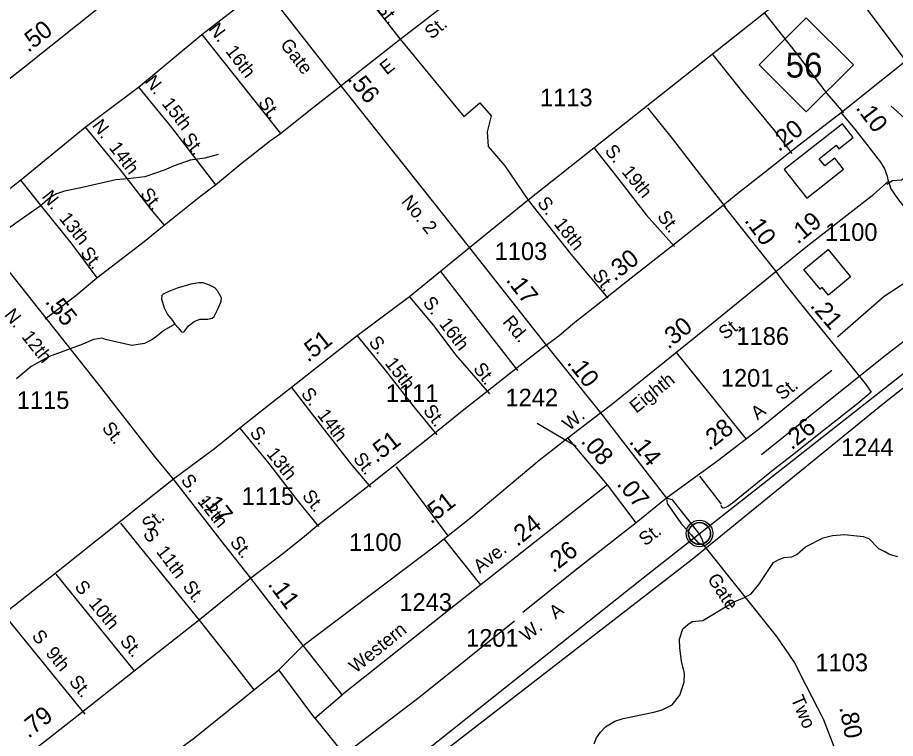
# Model space of a CAD drawing. Extents: x 2056842 to 2160602, y 826753 to 1016856.
# Drawn here: x 2067778 to 2073990, y 864781 to 869878 of the extents above; entities that cross this region are included whole.
import ezdxf

# ---------------------------------------------------------------- set-up
doc = ezdxf.new("R2010")
doc.units = 0
for name, color, linetype in [('Exist Boundary Land Use Reservation Military US Department of Defense', 7, 'Continuous'), ('Exist Civil Demographics Community CELL', 7, 'Continuous'), ('Exist Cultural Warehouse Building Footprint', 7, 'Continuous'), ('Exist Hydrographic Creek Single Shore', 7, 'Continuous'), ('Exist Hydrographic Misc Water Feature', 7, 'Continuous'), ('Exist Railroad Mainline', 7, 'Continuous'), ('Exist Railroad Siding', 7, 'Continuous'), ('Exist Road Non-System Type 51', 7, 'Continuous'), ('Exist Road Non-System Type 51 Label', 7, 'Continuous'), ('Exist Road Primary NC Attributed', 7, 'Continuous'), ('Exist Road Primary NC Service Mileage Hundredths English Label', 7, 'Continuous'), ('Exist Road Primary NC Shield CELL', 7, 'Continuous'), ('Exist Road Primary NC Shield Number Label', 7, 'Continuous'), ('Exist Road Secondary Mileage Hundredths English Label', 7, 'Continuous'), ('Exist Road Secondary Type 51 Attributed', 7, 'Continuous'), ('Exist Road Secondary Type 51 Divided Attributed', 7, 'Continuous'), ('Exist Road Secondary Type 51 Label', 7, 'Continuous'), ('Exist Road Secondary Type 51 Number Label', 7, 'Continuous')]:
    doc.layers.add(name, color=color, linetype=linetype)

msp = doc.modelspace()

# ---------------------------------------------------------------- linework, layer by layer
at = {"layer": 'Exist Boundary Land Use Reservation Military US Department of Defense'}
msp.add_lwpolyline([(2079729.3, 873057.2), (2079217.9, 872231.6), (2078917.6, 871495.8), (2078852.5, 871275.5), (2078751.7, 871162.9), (2076995.4, 869694.7), (2075448.8, 868458.6), (2072205.6, 865914.9), (2069683.3, 863910.7), (2068119, 862645.9), (2067327.2, 862021.6)], dxfattribs=at)
at = {"layer": 'Exist Civil Demographics Community CELL'}
msp.add_lwpolyline([(2072526, 866242.3), (2072527, 866247.9), (2072528.8, 866254.5), (2072531.7, 866261.7), (2072534.6, 866267.4), (2072538, 866273.2), (2072541.7, 866278.3), (2072545.7, 866282.6), (2072550.3, 866287.2), (2072555.8, 866291.8), (2072561.2, 866295.5), (2072566.1, 866298.4), (2072571.2, 866300.8), (2072576.6, 866303.1), (2072582.3, 866304.9), (2072586.6, 866306.1), (2072591.5, 866306.8), (2072595.6, 866307.5), (2072601.9, 866307.8), (2072606.4, 866307.7), (2072612, 866307.4), (2072616.9, 866306.7), (2072621.9, 866305.7), (2072626.9, 866304.3), (2072632, 866302.4), (2072638.7, 866299.4), (2072644.9, 866296), (2072650, 866292.4), (2072655.2, 866288.4), (2072658.5, 866285.3), (2072662.6, 866280.9), (2072666.5, 866276.2), (2072669.5, 866271.6), (2072672.7, 866266.6), (2072675.1, 866261.4), (2072677.2, 866256.4), (2072678.7, 866251.4), (2072680, 866246.8), (2072681.1, 866240.7), (2072681.7, 866236.1), (2072682, 866230.1), (2072681.8, 866224.3), (2072681.2, 866218.6), (2072680.3, 866213.1), (2072678.7, 866206.9), (2072676.8, 866201.1), (2072674.5, 866196), (2072671.3, 866190), (2072668, 866184.7), (2072664.6, 866180), (2072660.4, 866175.3), (2072655.1, 866170.3), (2072650.1, 866166.2), (2072645, 866162.7), (2072640.7, 866160.2), (2072633.9, 866157), (2072626.8, 866154.3), (2072620.8, 866152.8), (2072614.2, 866151.5), (2072609.8, 866151.1), (2072605.3, 866150.8), (2072599.7, 866150.8), (2072595.4, 866151.2), (2072589.8, 866151.9), (2072583.9, 866153.2), (2072579.3, 866154.5), (2072574.1, 866156.4), (2072569.5, 866158.4), (2072565.6, 866160.7), (2072558.8, 866164.7), (2072553.2, 866169), (2072548.3, 866173.5), (2072543.8, 866178.3), (2072540.7, 866182.3), (2072537.7, 866186.5), (2072533.6, 866193.6), (2072531.9, 866197.1), (2072530.2, 866201.1), (2072527.6, 866209.3), (2072526, 866216.4), (2072525.3, 866221.5), (2072525, 866227.9), (2072525, 866232.6), (2072525.5, 866239)], close=True, dxfattribs=at)
for centre, radius in [((2072603.6, 866229.9), 94.3), ((2072603.4, 866230.2), 76.7)]:
    msp.add_circle(centre, radius, dxfattribs=at)
at = {"layer": 'Exist Cultural Warehouse Building Footprint'}
for points in [[(2073614.1, 869127.4), (2073203.4, 868803.4), (2073362.8, 868601.2), (2073623.1, 868806.5), (2073561.3, 868884.8), (2073490.9, 868829.3), (2073451, 868879.9), (2073571.1, 868974.6), (2073590.1, 868950.6), (2073690.9, 869030.1)], [(2073512.7, 868237.5), (2073672.1, 868044.1), (2073516, 867915.3), (2073471.4, 867969.4), (2073457.7, 867958.1), (2073342.8, 868097.5)]]:
    msp.add_lwpolyline(points, close=True, dxfattribs=at)
at = {"layer": 'Exist Hydrographic Creek Single Shore'}
for points in [[(2069198.2, 868909.3), (2069104.7, 868883), (2069000.5, 868870.8), (2068886.7, 868830.4), (2068816.4, 868798.5), (2068678.8, 868752.4), (2068558.6, 868738.1), (2068474.8, 868729.8), (2068227.1, 868673.6), (2068111.2, 868651.1), (2068053, 868631.1), (2068009.1, 868604.8), (2067939.2, 868544.9), (2067765.3, 868424.7), (2067609.5, 868310.4), (2067545.7, 868254.3)], [(2068891.6, 867709.5), (2068814.3, 867665.1), (2068761.1, 867623.3), (2068728.2, 867599.3), (2068677.6, 867572.6), (2068587.7, 867558.7), (2068401.7, 867600.5), (2068376.4, 867611.9), (2068315.6, 867600.5), (2068240.9, 867568.8), (2067997.8, 867478.9), (2067874.9, 867410.5), (2067769.9, 867324.3)], [(2071858.2, 864741.9), (2071874.1, 864785.8), (2071904.1, 864826), (2071938.1, 864861.9), (2072003.9, 864902.2), (2072063.9, 864922.3), (2072279.7, 864966.7), (2072339.8, 864982.8), (2072409.6, 865018.8), (2072463.6, 865086.9), (2072495.3, 865179.1), (2072497.3, 865239), (2072477.2, 865327.1), (2072464.9, 865418.9), (2072462.8, 865483), (2072486.7, 865554.9), (2072520.5, 865587), (2072552.6, 865607.1), (2072626.5, 865615.2), (2072846.3, 865745.7), (2072916.3, 865773.9), (2072968.1, 865803.8), (2073024, 865868), (2073127.9, 866024.1), (2073159.7, 866044.3), (2073203.6, 866060.4), (2073255.7, 866064.5), (2073293.7, 866084.5), (2073353.6, 866136.5), (2073477.3, 866198.7), (2073545.5, 866214.9), (2073629.4, 866223), (2073761.4, 866209.3), (2073801.5, 866193.4), (2073869.6, 866123.6), (2073913.3, 866101.8)], [(2074007.9, 866065.8), (2073971.9, 866073.7), (2073943.9, 866083.5), (2073913.3, 866101.8)]]:
    msp.add_lwpolyline(points, dxfattribs=at)
at = {"layer": 'Exist Hydrographic Misc Water Feature'}
msp.add_lwpolyline([(2068891.6, 867709.5), (2068915.6, 867682.9), (2068938.4, 867656.3), (2068952.3, 867652.5), (2068962.5, 867662.6), (2068989.1, 867698.1), (2069027, 867729.7), (2069067.6, 867745), (2069125.8, 867746.2), (2069154.9, 867752.6), (2069170.1, 867765.2), (2069192.9, 867810.8), (2069218.2, 867869.1), (2069220.8, 867897), (2069194.2, 867945.1), (2069173.9, 867966.7), (2069132.1, 867988.2), (2069092.9, 868003.4), (2069061.2, 868003.4), (2069004.2, 867992), (2068906.8, 867964.1), (2068848.5, 867940.1), (2068808, 867921.1), (2068800.4, 867912.2), (2068797.9, 867889.4), (2068815.6, 867826), (2068838.4, 867777.9), (2068873.8, 867734.8), (2068891.6, 867709.5)], dxfattribs=at)
at = {"layer": 'Exist Railroad Mainline'}
msp.add_lwpolyline([(2077141.8, 869689), (2077103.2, 869658.3), (2073909.4, 867150.4), (2072551.8, 866045), (2070604.6, 864539.6), (2068671.2, 863006.8), (2068469.9, 862844.9), (2068294.9, 862704.5), (2068034.7, 862501.8), (2067817.2, 862332.3), (2067721.7, 862256.3)], dxfattribs=at)
at = {"layer": 'Exist Railroad Siding'}
for points in [[(2075214.7, 868475), (2074492.9, 867928.2), (2073908.4, 867478.5), (2073042.4, 866786)], [(2075214.7, 868475), (2074727.7, 868402.3), (2074340.2, 868185.8), (2073911.2, 867904.7), (2073578.9, 867618.9)]]:
    msp.add_lwpolyline(points, dxfattribs=at)
at = {"layer": 'Exist Road Non-System Type 51'}
for p, q in [((2073534.9, 870276.7), (2074062.8, 869570.7)), ((2068634.7, 869386.8), (2069083.1, 869757.9)), ((2068257.9, 869102.1), (2068634.7, 869386.8)), ((2067799.8, 868728.7), (2068257.9, 869102.1)), ((2067436.4, 868444), (2067799.8, 868728.7)), ((2070770.5, 868081.8), (2071316.4, 867381.7)), ((2072437.3, 867510.3), (2072933.4, 866896.6)), ((2070457.8, 866701.1), (2070822.8, 866212.3)), ((2068507.3, 866303.9), (2069073.8, 865605)), ((2071056.5, 865866.2), (2070796.4, 866191.1)), ((2068049.9, 865942.7), (2068602.8, 865257.6)), ((2070958, 865788), (2070076.3, 865088.1)), ((2067679.3, 865659), (2068254.4, 864952.4)), ((2070076.3, 865088.1), (2069800.3, 865437.4)), ((2069882.6, 864924.1), (2069626.8, 865266.7)), ((2069882.6, 864924.1), (2070076.3, 865088.1))]:
    msp.add_line(p, q, dxfattribs=at)
for points in [[(2070485.6, 869724.4), (2071117.9, 870214.1), (2071529.8, 870554.7), (2071803.1, 870758.1)], [(2069083.1, 869757.9), (2069651.4, 870198.4), (2069936.6, 870427.2)], [(2069936.6, 870427.2), (2070125.8, 870184.2), (2070485.6, 869724.4)], [(2073625.7, 869204.9), (2073506.1, 869341.7), (2073292.4, 869624.2), (2073066.3, 869908.5)], [(2069083.1, 869757.9), (2069302.1, 869482.2), (2069638.7, 869058.8)], [(2070044.1, 869378.5), (2070233.8, 869526.1), (2070485.6, 869724.4)], [(2070485.6, 869724.4), (2070936.6, 869177.6), (2071049.8, 869276), (2071130.2, 869183.6), (2071100.4, 869070.3), (2071109.3, 868966), (2071225.5, 868828.8), (2071390.5, 868587.8)], [(2072697.6, 869614.1), (2072909.5, 869348.4), (2073126.3, 869085.3), (2073255.9, 868916.9)], [(2068634.7, 869386.8), (2068867.1, 869100.6), (2069179.2, 868695.9)], [(2069638.7, 869058.8), (2069872.6, 869245.2), (2070044.1, 869378.5)], [(2072236.6, 869239.2), (2072419.1, 869010.4), (2072584.4, 868795.7), (2072785.9, 868539)], [(2073928.8, 868699.6), (2073967.9, 868726), (2074033.5, 868730.4), (2074310.6, 868942.1), (2074347.8, 869012.2), (2074335.9, 869082.2), (2074281.5, 869136.6), (2074074.4, 869147.1), (2073958.3, 869252.9)], [(2068257.9, 869102.1), (2068503.7, 868802.4), (2068724.1, 868519.2), (2068816.5, 868408.9)], [(2069179.2, 868695.9), (2069359.4, 868843.4), (2069567.2, 869008.2), (2069638.7, 869058.8)], [(2071857.5, 868955.2), (2072033.3, 868733.1), (2072225.4, 868484.2), (2072425.8, 868258.4)], [(2067799.8, 868728.7), (2067957, 868529.7), (2068162.5, 868276.3), (2068340.5, 868037)], [(2068816.5, 868408.9), (2069076.4, 868616.9), (2069179.2, 868695.9)], [(2071390.5, 868587.8), (2071692.2, 868205.5), (2071955.1, 867893.2)], [(2068340.5, 868037), (2068675, 868295.6), (2068816.5, 868408.9)], [(2067974.8, 867747.1), (2068191.6, 867911.8), (2068340.5, 868037)], [(2070551.9, 867902.1), (2070722.4, 867701.6), (2070878.8, 867491.5), (2071117.9, 867216.4)], [(2070181.7, 867627.1), (2070369.4, 867396.1), (2070591.7, 867112.5), (2070745.5, 866926.5)], [(2069717.7, 867261.2), (2069933.3, 866982), (2070134.4, 866725.7), (2070275.5, 866558.3)], [(2069350.5, 866974.2), (2069555.3, 866725.3), (2069753.4, 866467.4), (2069908.7, 866280)], [(2072603.6, 866634.8), (2072749.4, 866446.6), (2072757.4, 866436.9)], [(2069073.8, 865605), (2069287.2, 865333.2), (2069449.2, 865123.3)], [(2069882.6, 864924.1), (2070088.2, 864667.7), (2070630.4, 865079.1), (2071294.8, 865611.4)]]:
    msp.add_lwpolyline(points, dxfattribs=at)
at = {"layer": 'Exist Road Primary NC Attributed'}
for points in [[(2073605.9, 869207.8), (2074446.4, 869879.4), (2074652.8, 870041.2), (2075203.2, 870477.2), (2075559.9, 870753.7)], [(2072771.9, 868550.5), (2072875.1, 868635.4), (2073069.3, 868790.1), (2073287.1, 868961.9), (2073605.9, 869207.8)], [(2071517.7, 867560.5), (2071611, 867629.8), (2071721.7, 867723.6), (2071937.8, 867893.3), (2072119.9, 868037.6), (2072402.5, 868260.2), (2072771.9, 868550.5)]]:
    msp.add_lwpolyline(points, dxfattribs=at)
at = {"layer": 'Exist Road Primary NC Shield CELL'}
msp.add_lwpolyline([(2073026, 869543.5), (2073359, 869876.5), (2073692, 869543.5), (2073359, 869210.5)], close=True, dxfattribs=at)
at = {"layer": 'Exist Road Secondary Type 51 Attributed'}
for p, q in [((2070551.9, 867902.1), (2070181.7, 867627.1)), ((2070181.7, 867627.1), (2069717.7, 867261.2)), ((2070728.1, 866937.6), (2070267.1, 866569)), ((2071951.7, 866574.2), (2071672.6, 866905.6)), ((2070267.1, 866569), (2069896.1, 866280.7)), ((2071951.7, 866574.2), (2070958, 865788)), ((2072154.3, 866305.2), (2071951.7, 866574.2))]:
    msp.add_line(p, q, dxfattribs=at)
for points in [[(2076671.9, 872768.2), (2071390.5, 868587.8), (2070976, 868248.9)], [(2069141.2, 870568.8), (2068835.8, 870324.4), (2068386.7, 869973.3), (2067826.6, 869526.1), (2067231.5, 869060.3), (2067062.8, 868908.5)], [(2069141.2, 870568.8), (2069519.3, 870096), (2070065.6, 869395.3), (2070976, 868248.9)], [(2073939.6, 868720.5), (2073933.9, 868754.9), (2073913.3, 868812.2), (2073886.5, 868855.8), (2073705, 869088.3), (2073605.9, 869207.8)], [(2068882.3, 866613.9), (2068747.2, 866776), (2068357.7, 867276.1), (2067062.8, 868908.5)], [(2073144.5, 868081.8), (2073358.8, 868255.7), (2073836.4, 868628.1), (2073939.6, 868720.5)], [(2073939.6, 868720.5), (2073958.4, 868666.1), (2074005.1, 868597.9), (2074160.1, 868398.1), (2074344.8, 868174.5), (2074509.4, 867957.6), (2074577.9, 867877.2), (2074618.1, 867871.2)], [(2072771.9, 868550.5), (2073144.5, 868081.8)], [(2070976, 868248.9), (2070551.9, 867902.1)], [(2070976, 868248.9), (2071517.7, 867560.5)], [(2071903.7, 867083.1), (2071981.1, 867142.6), (2072662.6, 867691.9), (2073144.5, 868081.8)], [(2073144.5, 868081.8), (2073170.7, 868043.3), (2073206.7, 867995.2), (2073355.2, 867808.5), (2073638.1, 867460.6), (2073775.9, 867289.5), (2073817.2, 867228)], [(2071517.7, 867560.5), (2071313.3, 867401.9), (2071089.9, 867224.1)], [(2071517.7, 867560.5), (2071903.7, 867083.1)], [(2073540.4, 867381.2), (2073372.8, 867249.6), (2073039.9, 866979.1), (2072743.4, 866749.5), (2072370.9, 866479.7)], [(2069717.7, 867261.2), (2069554.6, 867133.7), (2069350.5, 866974.2)], [(2071089.9, 867224.1), (2070925, 867094.2), (2070728.1, 866937.6)], [(2073817.2, 867228), (2073722.8, 867148.5), (2073479.8, 866957.7), (2073260.5, 866784.1), (2073127.9, 866679.8), (2072837.2, 866443.8), (2072803.4, 866420.8), (2072793, 866415.1), (2072779.5, 866410.4), (2072771.5, 866409.5), (2072766.7, 866412.7), (2072755, 866428.3)], [(2071672.6, 866905.6), (2071903.7, 867083.1)], [(2071903.7, 867083.1), (2072370.9, 866479.7)], [(2069350.5, 866974.2), (2069282, 866919.1), (2069171, 866828.9), (2068882.3, 866613.9)], [(2069800.3, 865437.4), (2070743.3, 866148.4), (2070985.3, 866342.9), (2071468, 866748.4), (2071672.6, 866905.6)], [(2068882.3, 866613.9), (2068677.1, 866451.8), (2068494.3, 866306.1), (2068053, 865954.9), (2067673.8, 865654.7), (2067195.8, 865281.9), (2066793.8, 864958.7), (2066395.6, 864631.8), (2065774.9, 864160.6)], [(2069429.8, 865913.2), (2069243.2, 866150.6), (2068882.3, 866613.9)], [(2072370.9, 866479.7), (2072154.3, 866305.2)], [(2072154.3, 866305.2), (2071746.8, 865986.1), (2071352.5, 865670.7)], [(2069896.1, 866280.7), (2069808.3, 866207.9), (2069664.2, 866091.9), (2069429.8, 865913.2)], [(2074324.2, 863555.3), (2074200.8, 863648.2), (2074166.2, 863671.2), (2073945.3, 863820.7), (2073797.9, 863943.3), (2073727.3, 864047.2), (2073660.8, 864250.9), (2073645.2, 864405.8), (2073578.8, 864659.3), (2073481.1, 864917), (2073359.6, 865150.9), (2073272.4, 865323.4), (2073149.9, 865502.1), (2072636.1, 866145.1)], [(2069429.8, 865913.2), (2069291, 865800.4), (2069053.2, 865610.1), (2068602.8, 865256.1), (2068231.2, 864961.7), (2067771.9, 864600.3), (2067596.5, 864460.5), (2067389.9, 864292.4), (2066924.6, 863928.1), (2066573.8, 863652.9), (2066328.5, 863461.1), (2066307.2, 863441.6), (2066291.5, 863420.8), (2066292.2, 863396.5), (2066310.8, 863366.4), (2066374.5, 863286.9)], [(2069800.3, 865437.4), (2069602.2, 865689.3), (2069429.8, 865913.2)], [(2064684.1, 855839.6), (2064643.1, 855944), (2064589.1, 856124.9), (2064578.7, 856311.9), (2064608.8, 856568.6), (2064801, 857754.3), (2065030.5, 859012.8), (2065226.7, 860248.4), (2065364.9, 861035.1), (2065425.1, 861317.8), (2065553.9, 861629.5), (2065725.2, 861986), (2065930.8, 862276.9), (2066130.2, 862526.4), (2066317.1, 862696.8), (2066825, 863107.3), (2067775.2, 863846.1), (2068132.4, 864147.5), (2068556.1, 864440.6), (2069020.3, 864778.3), (2069626.8, 865266.7), (2069800.3, 865437.4)]]:
    msp.add_lwpolyline(points, dxfattribs=at)
at = {"layer": 'Exist Road Secondary Type 51 Divided Attributed'}
for points in [[(2072636.1, 866145.1), (2072624.2, 866182.7), (2072606.9, 866222.2), (2072540.5, 866307.6), (2072413.6, 866467.1), (2072370.9, 866479.7)], [(2072370.9, 866479.7), (2072374.7, 866441.4), (2072470.9, 866303.4), (2072545, 866219.8), (2072591, 866165.4), (2072636.1, 866145.1)]]:
    msp.add_lwpolyline(points, dxfattribs=at)
at = {"layer": 'Exist Road Secondary Type 51 Number Label'}
msp.add_line((2071730.3, 866845.6), (2071454.8, 867007.1), dxfattribs=at)

# ---------------------------------------------------------------- texts
at = {"layer": 'Exist Road Non-System Type 51 Label'}
for s, rotation, p in [('St.', 307.84994, (2070311.4, 869946)), ('N.  16th', 307.29465, (2069125.7, 869796.2)), ('St.', 39.94239, (2070708.2, 869720.3)), ('E', 38.31382, (2070389.1, 869468.6)), ('N.  15th', 307.55649, (2068674.4, 869425.3)), ('St.', 307.26117, (2069476.3, 869274.4)), ('N.  14th', 307.39131, (2068301.4, 869113.8)), ('St.', 307.85647, (2068936.1, 869017.8)), ('S.  19th', 308.96967, (2071928.3, 868933.6)), ('N.  13th', 308.48086, (2067945.8, 868610.3)), ('St.', 308.42863, (2068641.1, 868628.1)), ('S.  18th', 308.30676, (2071450.9, 868566.3)), ('St.', 307.29465, (2072299.3, 868469.9)), ('St.', 308.58374, (2068217.4, 868211.2)), ('St.', 307.29465, (2071839.5, 868055.2)), ('S.  16th', 307.29465, (2070641.3, 867862.3)), ('S.  15th', 307.55649, (2070258.1, 867582.3)), ('St.', 307.29465, (2070997.8, 867394.3)), ('S.  14th', 307.39131, (2069779.2, 867217.7)), ('St.', 307.55649, (2070643.3, 867097.7)), ('S.  13th', 308.48086, (2069416.1, 866941.4)), ('St.', 307.55649, (2070148.3, 866759)), ('S.  12th', 308.41383, (2068929.3, 866604.4)), ('St.', 308.48086, (2069787, 866493.4)), ('S  11th', 307.06667, (2068661.6, 866224.2)), ('St.', 308.41383, (2069276.3, 866166.8)), ('Ave.', 38.67346, (2071050, 865945)), ('S  10th', 309.76504, (2068177.1, 865851.1)), ('St.', 307.06667, (2068941.5, 865853.6)), ('Western', 38.81946, (2070170.8, 865237.8)), ('S  9th', 309.3838, (2067873.9, 865502.1)), ('St.', 309.76504, (2068497.6, 865465.9)), ('St.', 309.3838, (2068137.8, 865180.6))]:
    msp.add_text(s, height=95, rotation=rotation, dxfattribs=at).set_placement(p)
at = {"layer": 'Exist Road Primary NC Service Mileage Hundredths English Label'}
for s, rotation, p in [('.20', 37.91788, (2073164.9, 868925.2)), ('.30', 37.85822, (2072002.6, 868009.3))]:
    msp.add_text(s, height=125, rotation=rotation, dxfattribs=at).set_placement(p)
at = {"layer": 'Exist Road Primary NC Shield Number Label'}
msp.add_text('56', height=175, dxfattribs=at).set_placement((2073213.1, 869453.8))
at = {"layer": 'Exist Road Secondary Mileage Hundredths English Label'}
for s, rotation, p in [('.50', 38.22085, (2067853.7, 869626)), ('.56', 308.45329, (2070108.4, 869441.8)), ('.10', 307.38913, (2073704.1, 869238.1)), ('.19', 39.38426, (2073298.1, 868271)), ('.10', 306.01427, (2072917.1, 868442.1)), ('.17', 308.09228, (2071229.3, 868020.4)), ('.55', 308.4222, (2067968.3, 867867.5)), ('.21', 310.40832, (2073381.6, 867837.7)), ('.30', 38.86912, (2072382.7, 867528.2)), ('.51', 38.26131, (2069833.2, 867435.8)), ('.10', 307.9984, (2071661.1, 867434.7)), ('.26', 38.64638, (2073255.5, 866815.4)), ('.28', 38.44919, (2072672, 866810.9)), ('.51', 38.07568, (2070317.5, 866724.7)), ('.08', 310.11102, (2071759.2, 866879.1)), ('.14', 308.60188, (2072100.9, 866876.5)), ('.07', 309.67994, (2072013.4, 866576.9)), ('.17', 307.92507, (2069069.9, 866474.8)), ('.51', 37.87563, (2070704, 866292.3)), ('.24', 38.35025, (2071314.1, 866132.5)), ('.26', 37.70106, (2071568.9, 865946.6)), ('.11', 306.8698, (2069545, 865869.7)), ('.79', 37.94977, (2067855.8, 864777.6)), ('.80', 280.87554, (2073592.6, 865000))]:
    msp.add_text(s, height=125, rotation=rotation, dxfattribs=at).set_placement(p)
at = {"layer": 'Exist Road Secondary Type 51 Label'}
for s, rotation, p in [('Gate', 307.55311, (2069632.2, 869685.1)), ('No. 2', 309.18903, (2070489, 868574.7)), ('N.  12th', 308.41383, (2067680.1, 867774.3)), ('Rd.', 309.31801, (2071205.5, 867723.6)), ('St.', 38.34366, (2072784.9, 867595.6)), ('Eighth', 38.84058, (2072156.2, 867075.8)), ('St.', 38.44919, (2073188.4, 867167.6)), ('A', 38.44919, (2073014.1, 867029.2)), ('W.', 39.70809, (2071681.8, 866951.9)), ('St.', 308.41383, (2068371, 866974)), ('St.', 37.65984, (2068704, 866238.4)), ('St.', 37.70106, (2072219.6, 866137)), ('Gate', 303.45565, (2072655.2, 865908.8)), ('W.   A', 37.70106, (2071378.6, 865460.5)), ('Two', 293.30443, (2073247.4, 865061.5))]:
    msp.add_text(s, height=95, rotation=rotation, dxfattribs=at).set_placement(p)
at = {"layer": 'Exist Road Secondary Type 51 Number Label'}
for s, p in [('1113', (2071475.2, 869250.3)), ('1100', (2073490.9, 868298.5)), ('1103', (2071154.3, 868163.3)), ('1186', (2072865.1, 867563.3)), ('1201', (2072754.5, 867267.8)), ('1115', (2067773.2, 867110.4)), ('1111', (2070384.6, 867159.1)), ('1242', (2071230.8, 867128.4)), ('1244', (2073604.9, 866776.8)), ('1115', (2069363.7, 866431.8)), ('1100', (2070123.5, 866105.9)), ('1243', (2070480.2, 865682)), ('1201', (2070951.9, 865428.9)), ('1103', (2073424.1, 865255.4))]:
    msp.add_text(s, height=125, dxfattribs=at).set_placement(p)

doc.saveas('drawing.dxf')
